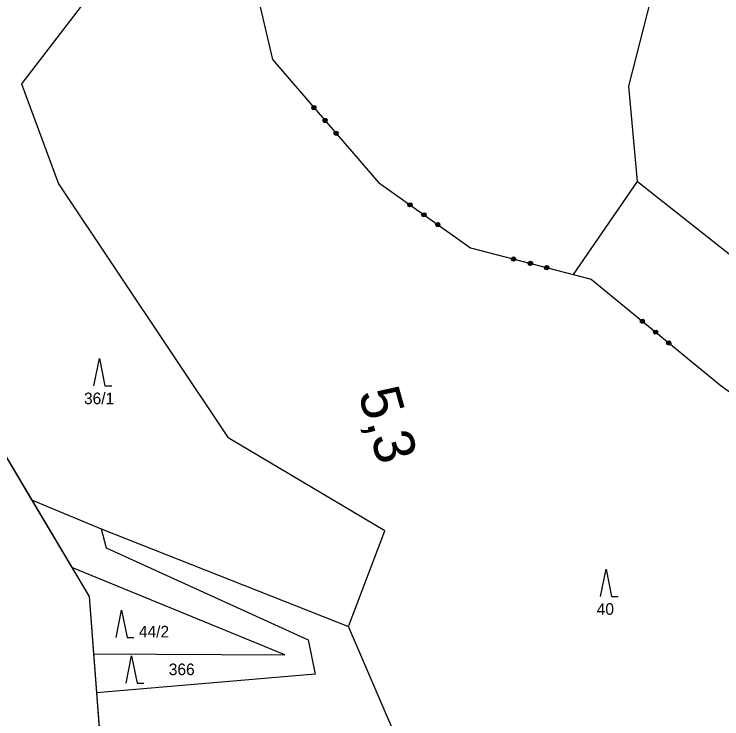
# Model space of a CAD drawing. Extents: x -866656 to -858817, y -1041816 to -1038653.
# Drawn here: x -864919.6 to -864815.8, y -1041046.4 to -1040943.1 of the extents above; entities that cross this region are included whole.
import ezdxf

# ---------------------------------------------------------------- set-up
doc = ezdxf.new("R2010")
doc.units = 0
for name, color, linetype in [('SZDC', 7, 'Continuous'), ('Vrstva 1', 7, 'Continuous'), ('Vrstva 3', 7, 'Continuous'), ('Vrstva 53', 7, 'Continuous'), ('Vrstva 7', 7, 'Continuous')]:
    doc.layers.add(name, color=color, linetype=linetype)

msp = doc.modelspace()

# ---------------------------------------------------------------- linework, layer by layer
at = {"layer": 'SZDC'}
msp.add_lwpolyline([(-864934.86, -1040933.14), (-864931.2, -1040972.04), (-864925.76, -1040999.58), (-864917, -1041014.31), (-864911.11, -1041024.22), (-864908.58, -1041028.48), (-864907.93, -1041036.91), (-864907.5, -1041042.63), (-864905.91, -1041063.49), (-864876.02, -1041096.59), (-864875.01, -1041097.53), (-864834, -1041135.62), (-864824.11, -1041144.81)], dxfattribs=at)
at = {"layer": 'Vrstva 1'}
for p, q in [((-864829.43, -1040953.64), (-864825.48, -1040938.24)), ((-864907.56, -1040939.09), (-864918.51, -1040953.31)), ((-864918.51, -1040953.31), (-864913.04, -1040967.97)), ((-864828.17, -1040967.63), (-864829.43, -1040953.64)), ((-864913.04, -1040967.97), (-864888.17, -1041005.22)), ((-864837.56, -1040981.28), (-864828.17, -1040967.63)), ((-864828.17, -1040967.63), (-864808.36, -1040983.3)), ((-864907.86, -1040997.59), (-864907.06, -1040993.59)), ((-864907.06, -1040993.59), (-864906.26, -1040997.59)), ((-864906.26, -1040997.59), (-864905.26, -1040997.59)), ((-864925.76, -1040999.58), (-864908.58, -1041028.48)), ((-864865.22, -1041018.85), (-864888.17, -1041005.22)), ((-864917, -1041014.31), (-864906.82, -1041018.55)), ((-864906.82, -1041018.55), (-864870.55, -1041032.92)), ((-864906.82, -1041018.55), (-864906.08, -1041021.37)), ((-864870.55, -1041032.92), (-864865.22, -1041018.85)), ((-864906.08, -1041021.37), (-864876.47, -1041034.84)), ((-864879.88, -1041037.07), (-864911.11, -1041024.22)), ((-864833.58, -1041028.48), (-864832.78, -1041024.48)), ((-864832.78, -1041024.48), (-864831.98, -1041028.48)), ((-864908.58, -1041028.48), (-864905.91, -1041063.49)), ((-864831.98, -1041028.48), (-864830.98, -1041028.48)), ((-864904.6, -1041034.5), (-864903.8, -1041030.5)), ((-864903.8, -1041030.5), (-864903, -1041034.5)), ((-864859.57, -1041058.28), (-864870.55, -1041032.92)), ((-864903, -1041034.5), (-864902, -1041034.5)), ((-864876.47, -1041034.84), (-864875.44, -1041039.88)), ((-864907.93, -1041036.91), (-864879.88, -1041037.07)), ((-864903.15, -1041041.22), (-864902.35, -1041037.22)), ((-864902.35, -1041037.22), (-864901.55, -1041041.22)), ((-864875.44, -1041039.88), (-864907.5, -1041042.63)), ((-864901.55, -1041041.22), (-864900.55, -1041041.22))]:
    msp.add_line(p, q, dxfattribs=at)
at = {"layer": 'Vrstva 3'}
for p, q in [((-864883.55, -1040941.82), (-864881.68, -1040949.76)), ((-864883.55, -1040941.82), (-864881.68, -1040949.76)), ((-864881.68, -1040949.76), (-864866.15, -1040967.76)), ((-864881.68, -1040949.76), (-864866.15, -1040967.76)), ((-864875.91, -1040956.91), (-864875.89, -1040956.63)), ((-864875.91, -1040956.91), (-864875.89, -1040956.63)), ((-864875.89, -1040956.63), (-864875.73, -1040956.5)), ((-864875.89, -1040956.63), (-864875.73, -1040956.5)), ((-864875.83, -1040956.85), (-864875.53, -1040956.59)), ((-864875.83, -1040956.85), (-864875.53, -1040956.59)), ((-864875.67, -1040956.57), (-864875.82, -1040956.71)), ((-864875.67, -1040956.57), (-864875.82, -1040956.71)), ((-864875.73, -1040956.5), (-864875.45, -1040956.52)), ((-864875.73, -1040956.5), (-864875.45, -1040956.52)), ((-864875.53, -1040956.59), (-864875.4, -1040956.74)), ((-864875.53, -1040956.59), (-864875.4, -1040956.74)), ((-864875.45, -1040956.52), (-864875.32, -1040956.67)), ((-864875.45, -1040956.52), (-864875.32, -1040956.67)), ((-864875.78, -1040957.06), (-864875.91, -1040956.91)), ((-864875.78, -1040957.06), (-864875.91, -1040956.91)), ((-864875.82, -1040956.71), (-864875.83, -1040956.85)), ((-864875.82, -1040956.71), (-864875.83, -1040956.85)), ((-864875.49, -1040957.08), (-864875.78, -1040957.06)), ((-864875.49, -1040957.08), (-864875.78, -1040957.06)), ((-864875.46, -1040956.66), (-864875.76, -1040956.92)), ((-864875.46, -1040956.66), (-864875.76, -1040956.92)), ((-864875.4, -1040956.74), (-864875.7, -1040957)), ((-864875.4, -1040956.74), (-864875.7, -1040957)), ((-864875.7, -1040957), (-864875.56, -1040957.01)), ((-864875.7, -1040957), (-864875.56, -1040957.01)), ((-864875.56, -1040957.01), (-864875.41, -1040956.88)), ((-864875.56, -1040957.01), (-864875.41, -1040956.88)), ((-864875.34, -1040956.95), (-864875.49, -1040957.08)), ((-864875.34, -1040956.95), (-864875.49, -1040957.08)), ((-864875.32, -1040956.67), (-864875.34, -1040956.95)), ((-864875.32, -1040956.67), (-864875.34, -1040956.95)), ((-864874.27, -1040958.8), (-864874.25, -1040958.52)), ((-864874.27, -1040958.8), (-864874.25, -1040958.52)), ((-864874.25, -1040958.52), (-864874.1, -1040958.39)), ((-864874.25, -1040958.52), (-864874.1, -1040958.39)), ((-864874.2, -1040958.74), (-864873.89, -1040958.48)), ((-864874.2, -1040958.74), (-864873.89, -1040958.48)), ((-864874.19, -1040958.6), (-864874.2, -1040958.74)), ((-864874.19, -1040958.6), (-864874.2, -1040958.74)), ((-864874.04, -1040958.47), (-864874.19, -1040958.6)), ((-864874.04, -1040958.47), (-864874.19, -1040958.6)), ((-864873.83, -1040958.55), (-864874.13, -1040958.81)), ((-864873.83, -1040958.55), (-864874.13, -1040958.81)), ((-864874.1, -1040958.39), (-864873.82, -1040958.41)), ((-864874.1, -1040958.39), (-864873.82, -1040958.41)), ((-864873.76, -1040958.63), (-864874.07, -1040958.89)), ((-864873.76, -1040958.63), (-864874.07, -1040958.89)), ((-864873.89, -1040958.48), (-864873.76, -1040958.63)), ((-864873.89, -1040958.48), (-864873.76, -1040958.63)), ((-864873.82, -1040958.41), (-864873.69, -1040958.56)), ((-864873.82, -1040958.41), (-864873.69, -1040958.56)), ((-864873.69, -1040958.56), (-864873.71, -1040958.85)), ((-864873.69, -1040958.56), (-864873.71, -1040958.85)), ((-864874.14, -1040958.96), (-864874.27, -1040958.8)), ((-864874.14, -1040958.96), (-864874.27, -1040958.8)), ((-864873.86, -1040958.98), (-864874.14, -1040958.96)), ((-864873.86, -1040958.98), (-864874.14, -1040958.96)), ((-864874.07, -1040958.89), (-864873.93, -1040958.9)), ((-864874.07, -1040958.89), (-864873.93, -1040958.9)), ((-864873.93, -1040958.9), (-864873.77, -1040958.77)), ((-864873.93, -1040958.9), (-864873.77, -1040958.77)), ((-864873.71, -1040958.85), (-864873.86, -1040958.98)), ((-864873.71, -1040958.85), (-864873.86, -1040958.98)), ((-864872.64, -1040960.7), (-864872.62, -1040960.42)), ((-864872.64, -1040960.7), (-864872.62, -1040960.42)), ((-864872.51, -1040960.85), (-864872.64, -1040960.7)), ((-864872.51, -1040960.85), (-864872.64, -1040960.7)), ((-864872.62, -1040960.42), (-864872.47, -1040960.28)), ((-864872.62, -1040960.42), (-864872.47, -1040960.28)), ((-864872.56, -1040960.63), (-864872.26, -1040960.37)), ((-864872.56, -1040960.63), (-864872.26, -1040960.37)), ((-864872.55, -1040960.49), (-864872.56, -1040960.63)), ((-864872.55, -1040960.49), (-864872.56, -1040960.63)), ((-864872.4, -1040960.36), (-864872.55, -1040960.49)), ((-864872.4, -1040960.36), (-864872.55, -1040960.49)), ((-864872.2, -1040960.45), (-864872.5, -1040960.71)), ((-864872.2, -1040960.45), (-864872.5, -1040960.71)), ((-864872.47, -1040960.28), (-864872.19, -1040960.31)), ((-864872.47, -1040960.28), (-864872.19, -1040960.31)), ((-864872.13, -1040960.52), (-864872.43, -1040960.78)), ((-864872.13, -1040960.52), (-864872.43, -1040960.78)), ((-864872.29, -1040960.79), (-864872.14, -1040960.66)), ((-864872.29, -1040960.79), (-864872.14, -1040960.66)), ((-864872.26, -1040960.37), (-864872.13, -1040960.52)), ((-864872.26, -1040960.37), (-864872.13, -1040960.52)), ((-864872.08, -1040960.74), (-864872.23, -1040960.87)), ((-864872.08, -1040960.74), (-864872.23, -1040960.87)), ((-864872.19, -1040960.31), (-864872.05, -1040960.46)), ((-864872.19, -1040960.31), (-864872.05, -1040960.46)), ((-864872.05, -1040960.46), (-864872.08, -1040960.74)), ((-864872.05, -1040960.46), (-864872.08, -1040960.74)), ((-864872.23, -1040960.87), (-864872.51, -1040960.85)), ((-864872.23, -1040960.87), (-864872.51, -1040960.85)), ((-864872.43, -1040960.78), (-864872.29, -1040960.79)), ((-864872.43, -1040960.78), (-864872.29, -1040960.79)), ((-864866.15, -1040967.76), (-864852.64, -1040977.38)), ((-864866.15, -1040967.76), (-864852.64, -1040977.38)), ((-864861.82, -1040970.97), (-864861.7, -1040970.81)), ((-864861.82, -1040970.97), (-864861.7, -1040970.81)), ((-864861.77, -1040971.25), (-864861.82, -1040970.97)), ((-864861.77, -1040971.25), (-864861.82, -1040970.97)), ((-864861.62, -1040970.86), (-864861.73, -1040971.03)), ((-864861.62, -1040970.86), (-864861.73, -1040971.03)), ((-864861.73, -1040971.03), (-864861.71, -1040971.17)), ((-864861.73, -1040971.03), (-864861.71, -1040971.17)), ((-864861.71, -1040971.17), (-864861.48, -1040970.84)), ((-864861.71, -1040971.17), (-864861.48, -1040970.84)), ((-864861.7, -1040970.81), (-864861.42, -1040970.76)), ((-864861.7, -1040970.81), (-864861.42, -1040970.76)), ((-864861.4, -1040970.9), (-864861.63, -1040971.22)), ((-864861.4, -1040970.9), (-864861.63, -1040971.22)), ((-864861.32, -1040970.96), (-864861.55, -1040971.28)), ((-864861.32, -1040970.96), (-864861.55, -1040971.28)), ((-864861.48, -1040970.84), (-864861.32, -1040970.96)), ((-864861.48, -1040970.84), (-864861.32, -1040970.96)), ((-864861.42, -1040970.76), (-864861.26, -1040970.88)), ((-864861.42, -1040970.76), (-864861.26, -1040970.88)), ((-864861.41, -1040971.26), (-864861.29, -1040971.1)), ((-864861.41, -1040971.26), (-864861.29, -1040971.1)), ((-864861.21, -1040971.15), (-864861.33, -1040971.32)), ((-864861.21, -1040971.15), (-864861.33, -1040971.32)), ((-864861.26, -1040970.88), (-864861.21, -1040971.15)), ((-864861.26, -1040970.88), (-864861.21, -1040971.15)), ((-864861.6, -1040971.36), (-864861.77, -1040971.25)), ((-864861.6, -1040971.36), (-864861.77, -1040971.25)), ((-864861.33, -1040971.32), (-864861.6, -1040971.36)), ((-864861.33, -1040971.32), (-864861.6, -1040971.36)), ((-864861.55, -1040971.28), (-864861.41, -1040971.26)), ((-864861.55, -1040971.28), (-864861.41, -1040971.26)), ((-864859.78, -1040972.42), (-864859.66, -1040972.26)), ((-864859.78, -1040972.42), (-864859.66, -1040972.26)), ((-864859.73, -1040972.7), (-864859.78, -1040972.42)), ((-864859.73, -1040972.7), (-864859.78, -1040972.42)), ((-864859.57, -1040972.81), (-864859.73, -1040972.7)), ((-864859.57, -1040972.81), (-864859.73, -1040972.7)), ((-864859.58, -1040972.31), (-864859.7, -1040972.48)), ((-864859.58, -1040972.31), (-864859.7, -1040972.48)), ((-864859.7, -1040972.48), (-864859.67, -1040972.62)), ((-864859.7, -1040972.48), (-864859.67, -1040972.62)), ((-864859.67, -1040972.62), (-864859.44, -1040972.29)), ((-864859.67, -1040972.62), (-864859.44, -1040972.29)), ((-864859.66, -1040972.26), (-864859.38, -1040972.21)), ((-864859.66, -1040972.26), (-864859.38, -1040972.21)), ((-864859.36, -1040972.35), (-864859.59, -1040972.67)), ((-864859.36, -1040972.35), (-864859.59, -1040972.67)), ((-864859.29, -1040972.77), (-864859.57, -1040972.81)), ((-864859.29, -1040972.77), (-864859.57, -1040972.81)), ((-864859.28, -1040972.41), (-864859.51, -1040972.73)), ((-864859.28, -1040972.41), (-864859.51, -1040972.73)), ((-864859.51, -1040972.73), (-864859.37, -1040972.71)), ((-864859.51, -1040972.73), (-864859.37, -1040972.71)), ((-864859.44, -1040972.29), (-864859.28, -1040972.41)), ((-864859.44, -1040972.29), (-864859.28, -1040972.41)), ((-864859.38, -1040972.21), (-864859.22, -1040972.33)), ((-864859.38, -1040972.21), (-864859.22, -1040972.33)), ((-864859.37, -1040972.71), (-864859.26, -1040972.55)), ((-864859.37, -1040972.71), (-864859.26, -1040972.55)), ((-864859.17, -1040972.6), (-864859.29, -1040972.77)), ((-864859.17, -1040972.6), (-864859.29, -1040972.77)), ((-864859.22, -1040972.33), (-864859.17, -1040972.6)), ((-864859.22, -1040972.33), (-864859.17, -1040972.6)), ((-864857.74, -1040973.87), (-864857.63, -1040973.71)), ((-864857.74, -1040973.87), (-864857.63, -1040973.71)), ((-864857.7, -1040974.15), (-864857.74, -1040973.87)), ((-864857.7, -1040974.15), (-864857.74, -1040973.87)), ((-864857.53, -1040974.26), (-864857.7, -1040974.15)), ((-864857.53, -1040974.26), (-864857.7, -1040974.15)), ((-864857.54, -1040973.76), (-864857.66, -1040973.93)), ((-864857.54, -1040973.76), (-864857.66, -1040973.93)), ((-864857.66, -1040973.93), (-864857.64, -1040974.07)), ((-864857.66, -1040973.93), (-864857.64, -1040974.07)), ((-864857.64, -1040974.07), (-864857.41, -1040973.74)), ((-864857.64, -1040974.07), (-864857.41, -1040973.74)), ((-864857.63, -1040973.71), (-864857.35, -1040973.66)), ((-864857.63, -1040973.71), (-864857.35, -1040973.66)), ((-864857.32, -1040973.8), (-864857.56, -1040974.12)), ((-864857.32, -1040973.8), (-864857.56, -1040974.12)), ((-864857.25, -1040974.22), (-864857.53, -1040974.26)), ((-864857.25, -1040974.22), (-864857.53, -1040974.26)), ((-864857.24, -1040973.86), (-864857.47, -1040974.18)), ((-864857.24, -1040973.86), (-864857.47, -1040974.18)), ((-864857.47, -1040974.18), (-864857.33, -1040974.16)), ((-864857.47, -1040974.18), (-864857.33, -1040974.16)), ((-864857.41, -1040973.74), (-864857.24, -1040973.86)), ((-864857.41, -1040973.74), (-864857.24, -1040973.86)), ((-864857.35, -1040973.66), (-864857.18, -1040973.78)), ((-864857.35, -1040973.66), (-864857.18, -1040973.78)), ((-864857.33, -1040974.16), (-864857.22, -1040974)), ((-864857.33, -1040974.16), (-864857.22, -1040974)), ((-864857.14, -1040974.05), (-864857.25, -1040974.22)), ((-864857.14, -1040974.05), (-864857.25, -1040974.22)), ((-864857.18, -1040973.78), (-864857.14, -1040974.05)), ((-864857.18, -1040973.78), (-864857.14, -1040974.05)), ((-864852.64, -1040977.38), (-864834.95, -1040981.96)), ((-864852.64, -1040977.38), (-864834.95, -1040981.96)), ((-864846.63, -1040979.04), (-864846.58, -1040978.85)), ((-864846.63, -1040979.04), (-864846.58, -1040978.85)), ((-864846.48, -1040979.28), (-864846.63, -1040979.04)), ((-864846.48, -1040979.28), (-864846.63, -1040979.04)), ((-864846.58, -1040978.85), (-864846.33, -1040978.7)), ((-864846.58, -1040978.85), (-864846.33, -1040978.7)), ((-864846.48, -1040978.87), (-864846.53, -1040979.07)), ((-864846.48, -1040978.87), (-864846.53, -1040979.07)), ((-864846.53, -1040979.07), (-864846.46, -1040979.19)), ((-864846.53, -1040979.07), (-864846.46, -1040979.19)), ((-864846.29, -1040979.33), (-864846.48, -1040979.28)), ((-864846.29, -1040979.33), (-864846.48, -1040979.28)), ((-864846.46, -1040979.19), (-864846.36, -1040978.8)), ((-864846.46, -1040979.19), (-864846.36, -1040978.8)), ((-864846.36, -1040978.8), (-864846.17, -1040978.85)), ((-864846.36, -1040978.8), (-864846.17, -1040978.85)), ((-864846.26, -1040978.82), (-864846.36, -1040979.21)), ((-864846.26, -1040978.82), (-864846.36, -1040979.21)), ((-864846.33, -1040978.7), (-864846.14, -1040978.75)), ((-864846.33, -1040978.7), (-864846.14, -1040978.75)), ((-864846.05, -1040979.19), (-864846.29, -1040979.33)), ((-864846.05, -1040979.19), (-864846.29, -1040979.33)), ((-864846.17, -1040978.85), (-864846.27, -1040979.24)), ((-864846.17, -1040978.85), (-864846.27, -1040979.24)), ((-864846.27, -1040979.24), (-864846.14, -1040979.17)), ((-864846.27, -1040979.24), (-864846.14, -1040979.17)), ((-864846.14, -1040978.75), (-864846, -1040979)), ((-864846.14, -1040978.75), (-864846, -1040979)), ((-864846.14, -1040979.17), (-864846.09, -1040978.97)), ((-864846.14, -1040979.17), (-864846.09, -1040978.97)), ((-864846, -1040979), (-864846.05, -1040979.19)), ((-864846, -1040979), (-864846.05, -1040979.19)), ((-864844.16, -1040979.47), (-864843.91, -1040979.33)), ((-864844.16, -1040979.47), (-864843.91, -1040979.33)), ((-864844.04, -1040979.81), (-864843.94, -1040979.43)), ((-864844.04, -1040979.81), (-864843.94, -1040979.43)), ((-864843.94, -1040979.43), (-864843.74, -1040979.48)), ((-864843.94, -1040979.43), (-864843.74, -1040979.48)), ((-864843.84, -1040979.45), (-864843.94, -1040979.84)), ((-864843.84, -1040979.45), (-864843.94, -1040979.84)), ((-864843.91, -1040979.33), (-864843.72, -1040979.38)), ((-864843.91, -1040979.33), (-864843.72, -1040979.38)), ((-864843.72, -1040979.38), (-864843.58, -1040979.62)), ((-864843.72, -1040979.38), (-864843.58, -1040979.62)), ((-864844.21, -1040979.67), (-864844.16, -1040979.47)), ((-864844.21, -1040979.67), (-864844.16, -1040979.47)), ((-864844.06, -1040979.91), (-864844.21, -1040979.67)), ((-864844.06, -1040979.91), (-864844.21, -1040979.67)), ((-864844.06, -1040979.5), (-864844.11, -1040979.69)), ((-864844.06, -1040979.5), (-864844.11, -1040979.69)), ((-864844.11, -1040979.69), (-864844.04, -1040979.81)), ((-864844.11, -1040979.69), (-864844.04, -1040979.81)), ((-864843.87, -1040979.96), (-864844.06, -1040979.91)), ((-864843.87, -1040979.96), (-864844.06, -1040979.91)), ((-864843.63, -1040979.82), (-864843.87, -1040979.96)), ((-864843.63, -1040979.82), (-864843.87, -1040979.96)), ((-864843.74, -1040979.48), (-864843.84, -1040979.86)), ((-864843.74, -1040979.48), (-864843.84, -1040979.86)), ((-864843.84, -1040979.86), (-864843.72, -1040979.79)), ((-864843.84, -1040979.86), (-864843.72, -1040979.79)), ((-864843.72, -1040979.79), (-864843.67, -1040979.6)), ((-864843.72, -1040979.79), (-864843.67, -1040979.6)), ((-864843.58, -1040979.62), (-864843.63, -1040979.82)), ((-864843.58, -1040979.62), (-864843.63, -1040979.82)), ((-864841.79, -1040980.29), (-864841.74, -1040980.1)), ((-864841.79, -1040980.29), (-864841.74, -1040980.1)), ((-864841.64, -1040980.54), (-864841.79, -1040980.29)), ((-864841.64, -1040980.54), (-864841.79, -1040980.29)), ((-864841.74, -1040980.1), (-864841.49, -1040979.96)), ((-864841.74, -1040980.1), (-864841.49, -1040979.96)), ((-864841.64, -1040980.12), (-864841.69, -1040980.32)), ((-864841.64, -1040980.12), (-864841.69, -1040980.32)), ((-864841.69, -1040980.32), (-864841.62, -1040980.44)), ((-864841.69, -1040980.32), (-864841.62, -1040980.44)), ((-864841.62, -1040980.44), (-864841.52, -1040980.05)), ((-864841.62, -1040980.44), (-864841.52, -1040980.05)), ((-864841.52, -1040980.05), (-864841.32, -1040980.1)), ((-864841.52, -1040980.05), (-864841.32, -1040980.1)), ((-864841.42, -1040980.08), (-864841.52, -1040980.46)), ((-864841.42, -1040980.08), (-864841.52, -1040980.46)), ((-864841.49, -1040979.96), (-864841.3, -1040980.01)), ((-864841.49, -1040979.96), (-864841.3, -1040980.01)), ((-864841.21, -1040980.44), (-864841.45, -1040980.59)), ((-864841.21, -1040980.44), (-864841.45, -1040980.59)), ((-864841.32, -1040980.1), (-864841.42, -1040980.49)), ((-864841.32, -1040980.1), (-864841.42, -1040980.49)), ((-864841.42, -1040980.49), (-864841.3, -1040980.42)), ((-864841.42, -1040980.49), (-864841.3, -1040980.42)), ((-864841.3, -1040980.01), (-864841.16, -1040980.25)), ((-864841.3, -1040980.01), (-864841.16, -1040980.25)), ((-864841.3, -1040980.42), (-864841.25, -1040980.22)), ((-864841.3, -1040980.42), (-864841.25, -1040980.22)), ((-864841.16, -1040980.25), (-864841.21, -1040980.44)), ((-864841.16, -1040980.25), (-864841.21, -1040980.44)), ((-864841.45, -1040980.59), (-864841.64, -1040980.54)), ((-864841.45, -1040980.59), (-864841.64, -1040980.54)), ((-864834.95, -1040981.96), (-864815.91, -1040997.62)), ((-864834.95, -1040981.96), (-864815.91, -1040997.62)), ((-864827.73, -1040988.03), (-864827.61, -1040987.87)), ((-864827.73, -1040988.03), (-864827.61, -1040987.87)), ((-864827.71, -1040988.31), (-864827.73, -1040988.03)), ((-864827.71, -1040988.31), (-864827.73, -1040988.03)), ((-864827.55, -1040988.43), (-864827.71, -1040988.31)), ((-864827.55, -1040988.43), (-864827.71, -1040988.31)), ((-864827.53, -1040987.93), (-864827.66, -1040988.09)), ((-864827.53, -1040987.93), (-864827.66, -1040988.09)), ((-864827.66, -1040988.09), (-864827.64, -1040988.23)), ((-864827.66, -1040988.09), (-864827.64, -1040988.23)), ((-864827.64, -1040988.23), (-864827.39, -1040987.92)), ((-864827.64, -1040988.23), (-864827.39, -1040987.92)), ((-864827.61, -1040987.87), (-864827.32, -1040987.84)), ((-864827.61, -1040987.87), (-864827.32, -1040987.84)), ((-864827.31, -1040987.98), (-864827.57, -1040988.29)), ((-864827.31, -1040987.98), (-864827.57, -1040988.29)), ((-864827.27, -1040988.41), (-864827.55, -1040988.43)), ((-864827.27, -1040988.41), (-864827.55, -1040988.43)), ((-864827.23, -1040988.05), (-864827.49, -1040988.36)), ((-864827.23, -1040988.05), (-864827.49, -1040988.36)), ((-864827.49, -1040988.36), (-864827.35, -1040988.34)), ((-864827.49, -1040988.36), (-864827.35, -1040988.34)), ((-864827.39, -1040987.92), (-864827.23, -1040988.05)), ((-864827.39, -1040987.92), (-864827.23, -1040988.05)), ((-864827.35, -1040988.34), (-864827.22, -1040988.19)), ((-864827.35, -1040988.34), (-864827.22, -1040988.19)), ((-864827.32, -1040987.84), (-864827.17, -1040987.97)), ((-864827.32, -1040987.84), (-864827.17, -1040987.97)), ((-864827.14, -1040988.25), (-864827.27, -1040988.41)), ((-864827.14, -1040988.25), (-864827.27, -1040988.41)), ((-864827.17, -1040987.97), (-864827.14, -1040988.25)), ((-864827.17, -1040987.97), (-864827.14, -1040988.25)), ((-864825.8, -1040989.61), (-864825.68, -1040989.46)), ((-864825.8, -1040989.61), (-864825.68, -1040989.46)), ((-864825.78, -1040989.89), (-864825.8, -1040989.61)), ((-864825.78, -1040989.89), (-864825.8, -1040989.61)), ((-864825.6, -1040989.52), (-864825.72, -1040989.68)), ((-864825.6, -1040989.52), (-864825.72, -1040989.68)), ((-864825.72, -1040989.68), (-864825.71, -1040989.82)), ((-864825.72, -1040989.68), (-864825.71, -1040989.82)), ((-864825.71, -1040989.82), (-864825.46, -1040989.51)), ((-864825.71, -1040989.82), (-864825.46, -1040989.51)), ((-864825.68, -1040989.46), (-864825.39, -1040989.43)), ((-864825.68, -1040989.46), (-864825.39, -1040989.43)), ((-864825.38, -1040989.57), (-864825.63, -1040989.88)), ((-864825.38, -1040989.57), (-864825.63, -1040989.88)), ((-864825.3, -1040989.64), (-864825.56, -1040989.94)), ((-864825.3, -1040989.64), (-864825.56, -1040989.94)), ((-864825.46, -1040989.51), (-864825.3, -1040989.64)), ((-864825.46, -1040989.51), (-864825.3, -1040989.64)), ((-864825.42, -1040989.93), (-864825.29, -1040989.78)), ((-864825.42, -1040989.93), (-864825.29, -1040989.78)), ((-864825.39, -1040989.43), (-864825.24, -1040989.56)), ((-864825.39, -1040989.43), (-864825.24, -1040989.56)), ((-864825.24, -1040989.56), (-864825.21, -1040989.84)), ((-864825.24, -1040989.56), (-864825.21, -1040989.84)), ((-864825.62, -1040990.02), (-864825.78, -1040989.89)), ((-864825.62, -1040990.02), (-864825.78, -1040989.89)), ((-864825.34, -1040989.99), (-864825.62, -1040990.02)), ((-864825.34, -1040989.99), (-864825.62, -1040990.02)), ((-864825.56, -1040989.94), (-864825.42, -1040989.93)), ((-864825.56, -1040989.94), (-864825.42, -1040989.93)), ((-864825.21, -1040989.84), (-864825.34, -1040989.99)), ((-864825.21, -1040989.84), (-864825.34, -1040989.99)), ((-864823.87, -1040991.2), (-864823.74, -1040991.05)), ((-864823.87, -1040991.2), (-864823.74, -1040991.05)), ((-864823.84, -1040991.48), (-864823.87, -1040991.2)), ((-864823.84, -1040991.48), (-864823.87, -1040991.2)), ((-864823.69, -1040991.61), (-864823.84, -1040991.48)), ((-864823.69, -1040991.61), (-864823.84, -1040991.48)), ((-864823.67, -1040991.11), (-864823.79, -1040991.26)), ((-864823.67, -1040991.11), (-864823.79, -1040991.26)), ((-864823.79, -1040991.26), (-864823.78, -1040991.41)), ((-864823.79, -1040991.26), (-864823.78, -1040991.41)), ((-864823.78, -1040991.41), (-864823.53, -1040991.1)), ((-864823.78, -1040991.41), (-864823.53, -1040991.1)), ((-864823.74, -1040991.05), (-864823.46, -1040991.02)), ((-864823.74, -1040991.05), (-864823.46, -1040991.02)), ((-864823.45, -1040991.16), (-864823.7, -1040991.47)), ((-864823.45, -1040991.16), (-864823.7, -1040991.47)), ((-864823.41, -1040991.58), (-864823.69, -1040991.61)), ((-864823.41, -1040991.58), (-864823.69, -1040991.61)), ((-864823.37, -1040991.22), (-864823.63, -1040991.53)), ((-864823.37, -1040991.22), (-864823.63, -1040991.53)), ((-864823.63, -1040991.53), (-864823.48, -1040991.52)), ((-864823.63, -1040991.53), (-864823.48, -1040991.52)), ((-864823.53, -1040991.1), (-864823.37, -1040991.22)), ((-864823.53, -1040991.1), (-864823.37, -1040991.22)), ((-864823.48, -1040991.52), (-864823.36, -1040991.36)), ((-864823.48, -1040991.52), (-864823.36, -1040991.36)), ((-864823.46, -1040991.02), (-864823.31, -1040991.15)), ((-864823.46, -1040991.02), (-864823.31, -1040991.15)), ((-864823.28, -1040991.43), (-864823.41, -1040991.58)), ((-864823.28, -1040991.43), (-864823.41, -1040991.58)), ((-864823.31, -1040991.15), (-864823.28, -1040991.43)), ((-864823.31, -1040991.15), (-864823.28, -1040991.43)), ((-864815.91, -1040997.62), (-864791.41, -1041015.06)), ((-864815.91, -1040997.62), (-864791.41, -1041015.06))]:
    msp.add_line(p, q, dxfattribs=at)
at = {"layer": 'Vrstva 53'}
msp.add_lwpolyline([(-864934.86, -1040933.14), (-864931.2, -1040972.04), (-864925.76, -1040999.58), (-864917, -1041014.31), (-864911.11, -1041024.22), (-864908.58, -1041028.48), (-864907.93, -1041036.91), (-864907.5, -1041042.63), (-864905.91, -1041063.49), (-864876.02, -1041096.59), (-864875.01, -1041097.53), (-864834, -1041135.62), (-864824.11, -1041144.81)], dxfattribs=at)

# ---------------------------------------------------------------- texts
at = {"layer": 'Vrstva 1'}
for s, p in [('36/1', (-864909.32, -1041000.29)), ('40', (-864834.14, -1041031.18)), ('44/2', (-864901.27, -1041034.5)), ('366', (-864896.89, -1041040.03))]:
    msp.add_text(s, height=1.7, dxfattribs=at).set_placement(p)
at = {"layer": 'Vrstva 7'}
msp.add_text('5,3', height=6, rotation=285.7848, dxfattribs=at).set_placement((-864869.13, -1040998.69))

doc.saveas('drawing.dxf')
